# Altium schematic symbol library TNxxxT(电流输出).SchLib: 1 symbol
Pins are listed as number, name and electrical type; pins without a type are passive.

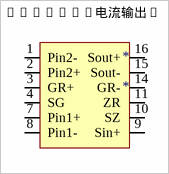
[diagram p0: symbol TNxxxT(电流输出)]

## TNxxxT(电流输出)
designator *
pins: 1 Pin2-, 2 Pin2+, 3 GR+, 4 SG, 7 Pin1+, 8 Pin1-, 9 Sin+, 10 SZ, 11 ZR, 14 GR-, 15 Sout-, 16 Sout+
